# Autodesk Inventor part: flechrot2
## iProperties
Shininess: 64.0
Length Units: 11269
Angle Units: 11279
Time Units: 11290
Mass Units: 11283
Length Display Precision: 3
Angle Display Precision: 2
Compacted: True
Part Number: flechrot2
Document SubType Name: Modeling
Created: 2003-10
Material: Par défaut
Designer: Maison
Density: 0.0
Volumn: 0.0
Area: 0.0
PropertySet Name: Model Information
Control State: 0
Master: False
Checked Out: False
Author: Maison
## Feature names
1. Extrusion1
